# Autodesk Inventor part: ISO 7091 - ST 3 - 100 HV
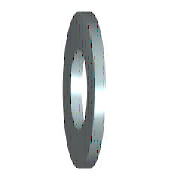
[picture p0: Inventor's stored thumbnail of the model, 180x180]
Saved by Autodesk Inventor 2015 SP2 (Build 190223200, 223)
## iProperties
IsCustomPart: 0
Created: 2012-02
Part Number: ISO 7091 - ST 3 - 100 HV
Material: Stahl
Description: Unterlegscheiben - normale Ausführung - Produktklasse C
Document SubType Name: Modeling
Standard: ISO 7091
Designer: Hübner
Standard Revision: Second edition 2000-06-01
Standards Organization: ISO
Language: de-DE
Size Designation: ST 3 - 100 HV
Categories: <MemberInstance><Categories><Category DisplayName="Verbindungselemente" InternalName="e4da775c-781d-43d5-af7c-5136215cf5a6" Mnemonic="FSTN"><Category DisplayNam
Density: 7.85 g/cm^3
Appearance: Platte
Author: Hübner
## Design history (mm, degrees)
sketch "Skizze"
  geometry: C1 r 3.5 at (0, 0); C2 r 1.7 at (0, 0); 1 further point
  constraints: 2 centre point, 2 coincident
  dimensions: "d0" = 3.4 diameter of C2 (= SD1); "d1" = 7 diameter of C1 (= SD2)
extrude "Körper" new body sketch "Skizze" distance "d2" = 0.5 (= SD); taper "d3" = 0 deg
workaxis "Work Axis1"
workplane "Work Plane1"
body "Solid1"
other parameters: "SD1" = 3.4 [user parameter; used in 1 equation term], "SD2" = 7 [user parameter; used in 1 equation term], "SD" = 0.5 [user parameter; used in 1 equation term], "d4" = 0, "d5" = 0, "d6" = 0, "d7" = 0, "NND" = 3 [user parameter]
